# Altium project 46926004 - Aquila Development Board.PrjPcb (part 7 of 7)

## Sheet 900_Display_Port.SchDoc: Aquila Development Board
size Letter; Organization: Toradex Solutions Inc.; Address1: 6415 Northwest Drive; Address2: Mississauga, ON, L4V 1X1; Address3: Canada; SheetNumber: 34; SheetTotal: 34
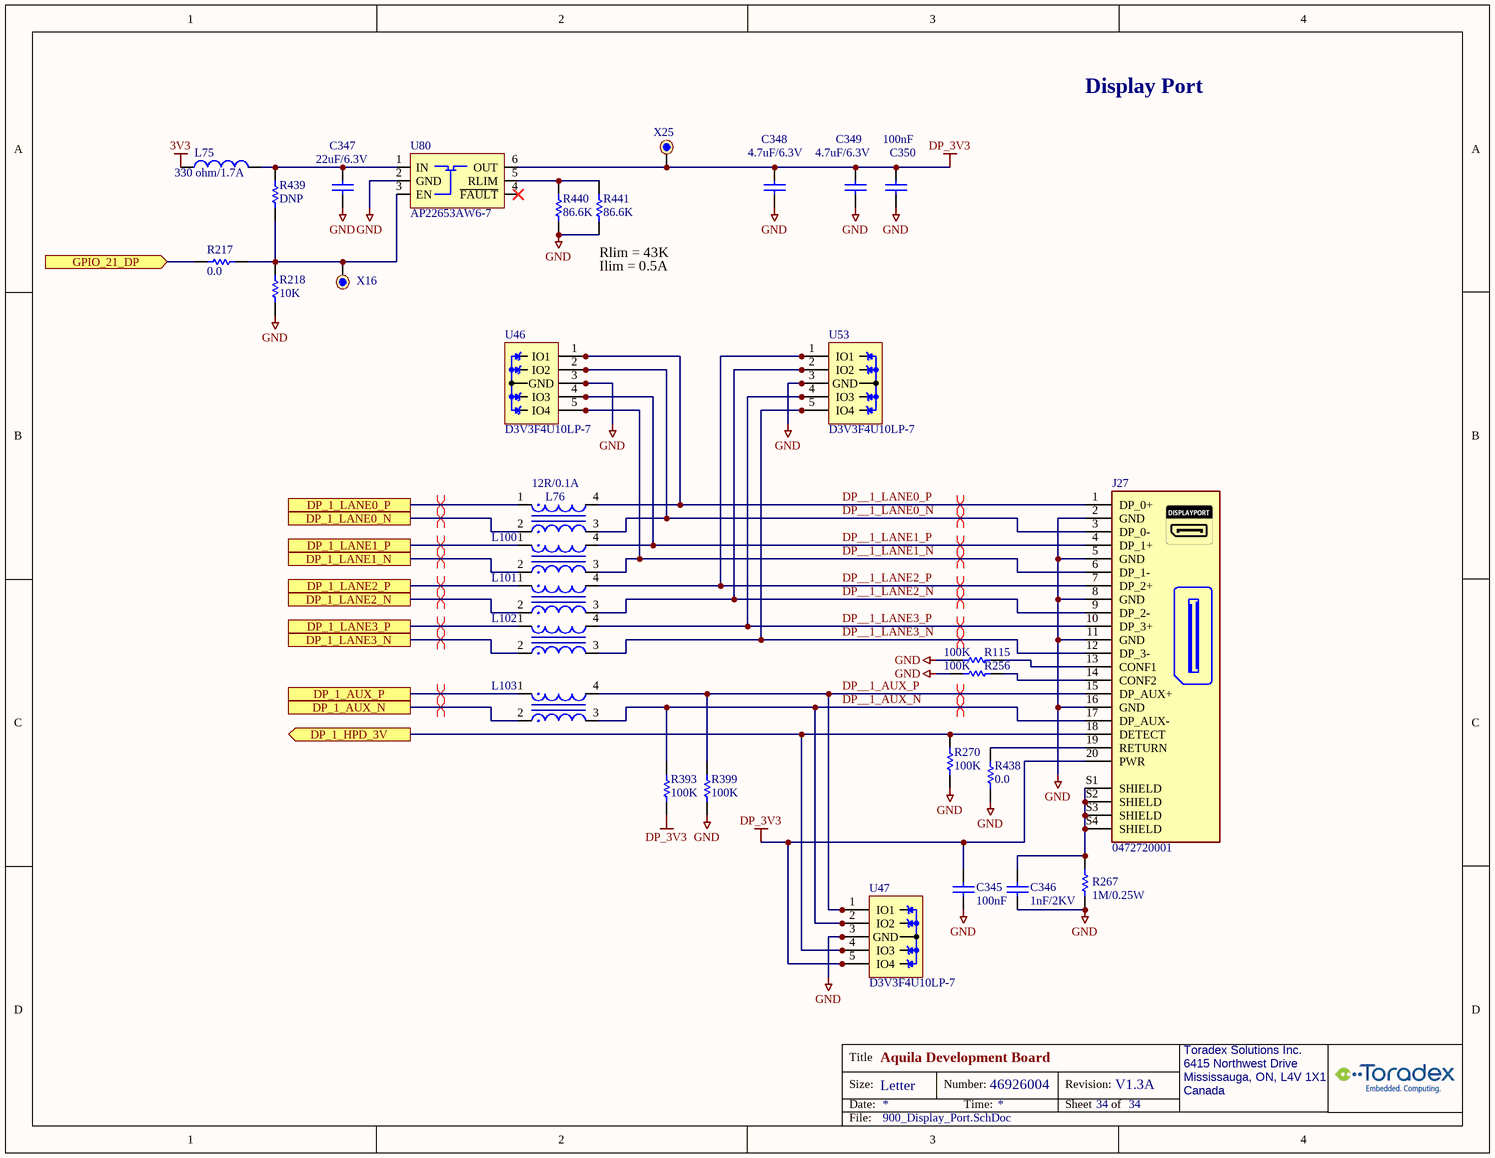
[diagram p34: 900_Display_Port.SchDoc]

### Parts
C345  100nF  [C0402_CAPC1005L]
C346  value 1nF/2KV  [C/1206]  (hidden comment: 0567-Cap-1206-1nF/2KV)
C347  22uF/6.3V  [C0402_CAPC1005L]
C348  value 4.7uF/6.3V  [C0402_CAPC1005L]  (hidden comment: 0354-Cap-0402-4.7uF/6.3V)
C349  value 4.7uF/6.3V  [C0402_CAPC1005L]  (hidden comment: 0354-Cap-0402-4.7uF/6.3V)
C350  100nF  [C0402_CAPC1005L]
J27  0472720001  [MOLEX_47272-0001]
L75  value 330 ohm/1.7A  [C/0603]  (hidden comment: 0405-Fer-0603-330ohm/1.7A)
L76  12R/0.1A  [COIL0302]
L100  12R/0.1A  [COIL0302]  (value not drawn)
L101  12R/0.1A  [COIL0302]  (value not drawn)
L102  12R/0.1A  [COIL0302]  (value not drawn)
L103  12R/0.1A  [COIL0302]  (value not drawn)
R115  value 100K  [R0402_RESC1005L]  (hidden comment: 1977-Res-0402-100K)
R217  value 0.0  [R/0603]  (hidden comment: 0195-Res-0603-0.0ohm)
R218  value 10K  [R0402_RESC1005L]  (hidden comment: 1572-Res-0402-10K)
R256  value 100K  [R0402_RESC1005L]  (hidden comment: 1977-Res-0402-100K)
R267  value 1M/0.25W  [R/1206]  (hidden comment: 1860-Res-1206-1M-5%-0.25W)
R270  value 100K  [R0402_RESC1005L]  (hidden comment: 1977-Res-0402-100K)
R393  value 100K  [R0402_RESC1005L]  (hidden comment: 1977-Res-0402-100K)
R399  value 100K  [R0402_RESC1005L]  (hidden comment: 1977-Res-0402-100K)
R438  value 0.0  [R/0603]  (hidden comment: 0195-Res-0603-0.0ohm)
R439  value DNP  [R/0603]  (hidden comment: 0000-Res-0603-DNP)
R440  value 86.6K  [R0402_RESC1005L]  (hidden comment: 1539-Res-0402-86.6k)
R441  value 86.6K  [R0402_RESC1005L]  (hidden comment: 1539-Res-0402-86.6k)
U46  D3V3F4U10LP-7  [10-UFDFN]
U47  D3V3F4U10LP-7  [10-UFDFN]
U53  D3V3F4U10LP-7  [10-UFDFN]
U80  AP22653AW6-7  [SOT23-6]
X16  000-TestPoint  [TestPoint_1]  (value not drawn)
X25  000-TestPoint  [TestPoint_1]  (value not drawn)

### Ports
DP_1_AUX_N, DP_1_AUX_P, DP_1_HPD_3V (out), DP_1_LANE0_N, DP_1_LANE0_P, DP_1_LANE1_N, DP_1_LANE1_P, DP_1_LANE2_N, DP_1_LANE2_P, DP_1_LANE3_N, DP_1_LANE3_P, GPIO_21_DP (in)

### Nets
3V3: L75.1
DP_3V3: C345.2 C348.2 C349.2 C350.2 J27.20(PWR) R393.1 U47.5(IO4) U47.6(NC) U80.6(OUT) X25.1
GND: C345.1 C346.1 C347.1 C348.1 C349.1 C350.1 J27.2(GND) J27.5(GND) J27.8(GND) J27.11(GND) J27.16(GND) R115.2 R218.2 R256.2 R267.2 R270.2 R399.1 R438.1 R440.1 R441.1 U46.3(GND) U46.8(GND) U47.3(GND) U47.8(GND) U53.3(GND) U53.8(GND) U80.2(GND)
DP_1_AUX_N: L103.2 ; port DP_1_AUX_N
DP_1_AUX_P: L103.1 ; port DP_1_AUX_P
DP_1_HPD_3V: J27.18(DETECT) R270.1 U47.4(IO3) U47.7(NC) ; port DP_1_HPD_3V
DP_1_LANE0_N: L76.2 ; port DP_1_LANE0_N
DP_1_LANE0_P: L76.1 ; port DP_1_LANE0_P
DP_1_LANE1_N: L100.2 ; port DP_1_LANE1_N
DP_1_LANE1_P: L100.1 ; port DP_1_LANE1_P
DP_1_LANE2_N: L101.2 ; port DP_1_LANE2_N
DP_1_LANE2_P: L101.1 ; port DP_1_LANE2_P
DP_1_LANE3_N: L102.2 ; port DP_1_LANE3_N
DP_1_LANE3_P: L102.1 ; port DP_1_LANE3_P
DP__1_AUX_N: J27.17(DP_AUX-) L103.3 R393.2 U47.2(IO2) U47.9(NC)
DP__1_AUX_P: J27.15(DP_AUX+) L103.4 R399.2 U47.1(IO1) U47.10(NC)
DP__1_LANE0_N: J27.3(DP_0-) L76.3 U46.2(IO2) U46.9(NC)
DP__1_LANE0_P: J27.1(DP_0+) L76.4 U46.1(IO1) U46.10(NC)
DP__1_LANE1_N: J27.6(DP_1-) L100.3 U46.5(IO4) U46.6(NC)
DP__1_LANE1_P: J27.4(DP_1+) L100.4 U46.4(IO3) U46.7(NC)
DP__1_LANE2_N: J27.9(DP_2-) L101.3 U53.2(IO2) U53.9(NC)
DP__1_LANE2_P: J27.7(DP_2+) L101.4 U53.1(IO1) U53.10(NC)
DP__1_LANE3_N: J27.12(DP_3-) L102.3 U53.5(IO4) U53.6(NC)
DP__1_LANE3_P: J27.10(DP_3+) L102.4 U53.4(IO3) U53.7(NC)
GPIO_21_DP: R217.2 ; port GPIO_21_DP
NetC346_2: C346.2 J27.S1(SHIELD) J27.S2(SHIELD) J27.S3(SHIELD) J27.S4(SHIELD) R267.1
NetC347_2: C347.2 L75.2 R439.1 U80.1(IN)
NetJ27_13: J27.13(CONF1) R115.1
NetJ27_14: J27.14(CONF2) R256.1
NetJ27_19: J27.19(RETURN) R438.2
NetR217_1: R217.1 R218.1 R439.2 U80.3(EN) X16.1
NetR440_2: R440.2 R441.2 U80.5(RLIM)

Not connected (* = marked no-connect by the designer): U80 4(~{FAULT})*

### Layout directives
differential pair; differential pair class DP: DP_1_AUX_N, DP_1_AUX_P, DP_1_LANE0_N, DP_1_LANE0_P, DP_1_LANE1_N, DP_1_LANE1_P, DP_1_LANE2_N, DP_1_LANE2_P, DP_1_LANE3_N, DP_1_LANE3_P
differential pair; differential pair class DP_CON: DP__1_AUX_N, DP__1_AUX_P, DP__1_LANE0_N, DP__1_LANE0_P, DP__1_LANE1_N, DP__1_LANE1_P, DP__1_LANE2_N, DP__1_LANE2_P, DP__1_LANE3_N, DP__1_LANE3_P

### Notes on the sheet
- Display Port
- (near R441) Rlim = 43K
- Ilim = 0.5A

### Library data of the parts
C345 C350 = 1566-Cap-0402-100nF/50V: (-55 to 125 DegC AEC) Cap Ceramic 0.1uF 50V X7R 10% 0402; MfrNo: GRT155R71H104KE01D; Mfr: Murata; Alt: CL05B104KB54PNC,GCM155R71H104ME02D,GCM155R71H104KE02D,GCM155R71H104KE02J; PN: 1566
C346 = 0567-Cap-1206-1nF/2KV: (-55 to 125 DegC) CAP CER 1000PF 2KV X7R 1206; Mfr: Johanson Dielectrics Inc.; MfrNo: 202R18W102KV4E; PN: 567; Alt: 478-2956-1-ND; Alt2: 399-4819-1-ND
C347 = 2404-Cap-0402-22uF/6.3V: (-55 to 85 DegC) CAP CER 22UF 6.3V 20% X5R 0402; MfrNo: GRM155R60J226ME11D; Mfr: Murata; PN: 2404
C348 C349 = 0354-Cap-0402-4.7uF/6.3V: (-55 to 85 DegC) CAP CER 4.7UF 6.3V 20% X5R 0402; MfrNo: GRM155R60J475ME87D; Mfr: Murata Electronics North America; PN: 354; Alt: 1276-1483-1-ND; Alt2: 490-5915-1-ND
J27 = 2274-CONN-DISPLAY-PORT: (-20 to 85 DegC) CONN RCPT DISPLAYPORT 20P SMD RA/TH; Mfr: Molex; MfrNo: 47272-0001; PN: 2274
L75 = 0405-Fer-0603-330ohm/1.7A: (-55 to 125 DegC) FERRITE BEAD 330 OHM 0603 1.7A 80mohm, typ 48mohm; Mfr: TDK Corporation; MfrNo: MPZ1608S331ATA00; PN: 405; TR: 445-5221-2-ND; DR: 445-5221-6-ND; DR2: 810-MPZ1608S331ATA00
L76 L100-L103 = 1371-Ind-0.8x0.6-12ohm/0.1A-Choke: (-40 to 85 DegC) Ind CMC Choke 12 Ohm 0.1A 1ohm 0.85x0.65x0.5mm; MfrNo: EXC-14CH120U; Mfr: Panasonic; PN: 1371
R115 R256 R270 R393 R399 = 1977-Res-0402-100K: (-55 to 155 DegC) RES 100K OHM 1/16W 1% 0402 SMD; Mfr: Yageo; MfrNo: RC0402FR-07100KL; PN: 1977
R217 R438 = 0195-Res-0603-0.0ohm: (-55 to 155 DegC) RES 0.0 OHM 1/10W JUMP 0603; Mfr: Samsung; MfrNo: RC1608J000CS; Alt: 311-0.0GRCT-ND; Alt2: A106051CT-ND; PN: 195; TR: 1276-3510-2-ND
R218 = 1572-Res-0402-10K: (-55 to 155 DegC AEC) RES 10K OHM 1% 1/16W 100ppm 0402; Mfr: Stackpole Electronics; MfrNo: RMCF0402FT10K0; Alt: AC0402FR-0710KL,AC0402FR-1310KL,CRGCQ0402F10K; PN: 1572
R267 = 1860-Res-1206-1M-5%-0.25W: (-55 to 155 DegC) RES SMD 1M OHM 5% 0.25W 10ppm 1206; Mfr: TE Connectivity; MfrNo: CRGCQ1206J1M0; PN: 1860; Alt: RMCF1206JT1M00, RMCF1206JG1M00, CR1206-JW-105ELF
R439 = 0000-Res-0603-DNP: RES 0603
R440 R441 = 1539-Res-0402-86.6k: (-55 to 155 DegC AEC) RES 86.6K OHM 1% 1/16W 100ppm 0402; Mfr: Stackpole Electronics; MfrNo: RMCF0402FT86K6; Alt: AC0402FR-0786K6L,RK73H1ETTP8662F,ERJ-2RKF8662X; PN: 1539
U46 U47 U53 = 1463-D3V3F4U10LP: (-55 to 150 DegC) IC TVS DIODE 4ch Vrm:3.3V Vbr:6.2 Vcl:5V@16A 12KV/12KV 0.5pF 10-UFDFN 0.5mm; Mfr: Diodes; PN: 1463; Notes: Similar: PN1317
U80 = 1475-AP22653: (-40 to 85 DegC) IC PWR SWITCH 3-5.5V EN-Active-High ENth:1.5V With-Discharge 65mohm typ ADJ 0.1-2.1A 6SSOP; Mfr: Diodes; PN: 1475; Note: Similar: BD2222G, BD2242G, TPS25221, TPS2553, RT9728A, RT9728B, RT9728C, AP2553, MIC2009YM6, MIC2019YM6, MIC2009A-1YM6,MIC2019A-1YM6
X16 X25 = 000-TestPoint: TestPoint TH; Note: this is PCB footprint only, no parts to buy or assemble

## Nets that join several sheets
1V8: 200_Aquila (R66.1), 600_Peripherals (14 pins), 100_Power_1 (J15.6 J16.6), 210_Translators (6 pins), 300_USB1_OTG (L21.1 R108.1 R118.1), 310_USB3 (R140.1 R141.1), 400_M2_KeyB (R182.1 R193.1 R418.2), 420_MIPI_DSI (16 pins), 500_CAN (L57.1), 120_Power_2 (Q5.1 R39.2 X19.1), 140_Power_3 (C8.2 U3.2), 360_Ethernet2 (5 pins), 410_M2_KeyM (R198.1), 540_Audio (6 pins), 620_Peripherals2 (15 pins), 225_Debug2 (8 pins), 227_JTAG (C239.2 R284.2 U61.1 U61.16), 215_Translators2 (25 pins), 800_Jumpers (10 pins), 810_Jumpers (18 pins), 510_ISO_CAN (L72.1), 700_RS232_RS485 (10 pins), 315_USBC_DFP (R391.2 R392.1), 445_CSI_1 (7 pins), 450_CSI_2 (7 pins)
3V3: 200_Aquila (R459.1), 100_Power_1 (J15.4 J15.5 J16.4 J16.5), 210_Translators (9 pins), 220_Debug (L15.1), 300_USB1_OTG (10 pins), 305_USB_Hub (C129.2 L31.2 Q13.2 R135.2), 350_Ethernet (J34.11 J34.13), 230_SD_Card (L20.1), 400_M2_KeyB (L46.1 L47.1), 420_MIPI_DSI (6 pins), 120_Power_2 (6 pins), 140_Power_3 (7 pins), 360_Ethernet2 (J36.11 J36.13 L41.2 L42.2), 410_M2_KeyM (L48.1 L49.1), 225_Debug2 (6 pins), 215_Translators2 (14 pins), 810_Jumpers (J13.9 J13.10), 325_USB_PowerDelivery (R402.1 R403.1), 700_RS232_RS485 (L79.1 L80.1), 315_USBC_DFP (5 pins), 445_CSI_1 (7 pins), 450_CSI_2 (7 pins), 900_Display_Port (L75.1)
3V3_UHUB: 200_Aquila (R65.1), 305_USB_Hub (18 pins)
5V: 120_Power_2 (7 pins), 140_Power_3 (7 pins), 160_Power_4 (11 pins)
5V_S: 100_Power_1 (J15.2 J16.2), 300_USB1_OTG (5 pins), 310_USB3 (L32.1 L33.1), 305_USB_Hub (R123.2), 420_MIPI_DSI (6 pins), 500_CAN (L56.1), 120_Power_2 (R40.2), 140_Power_3 (Q3.D R24.2 X11.1), 360_Ethernet2 (R159.2 R160.2), 620_Peripherals2 (13 pins), 510_ISO_CAN (L71.1), 315_USBC_DFP (6 pins), 445_CSI_1 (C316.2 J70.21), 450_CSI_2 (C322.2 J71.21)
5V_STB: 100_Power_1 (C4.2 U1.3 X1.1), 120_Power_2 (7 pins)
5V_T: 200_Aquila (28 pins), 600_Peripherals (R239.1 R358.1), 140_Power_3 (6 pins), 227_JTAG (L66.1)
12V: 120_Power_2 (10 pins), 620_Peripherals2 (C237.2 J56.2 R274.2 U40.2)
D_1V8_LDO: 220_Debug (C41.1 U86.5), 225_Debug2 (J63.1)
FT_3V3: 220_Debug (D12.3 X30.1), 225_Debug2 (10 pins), 227_JTAG (C240.2 U61.15)
GND: 200_Aquila (111 pins), 600_Peripherals (26 pins), 100_Power_1 (19 pins), 210_Translators (9 pins), 220_Debug (15 pins), 300_USB1_OTG (36 pins), 310_USB3 (30 pins), 305_USB_Hub (37 pins), 350_Ethernet (7 pins), 230_SD_Card (14 pins), 400_M2_KeyB (41 pins), 420_MIPI_DSI (20 pins), 500_CAN (18 pins), 120_Power_2 (58 pins), 140_Power_3 (10 pins), 360_Ethernet2 (67 pins), 410_M2_KeyM (39 pins), 540_Audio (39 pins), 620_Peripherals2 (32 pins), 225_Debug2 (58 pins), 227_JTAG (14 pins), 215_Translators2 (20 pins), 800_Jumpers (8 pins), 810_Jumpers (18 pins), 160_Power_4 (30 pins), 510_ISO_CAN (18 pins), 325_USB_PowerDelivery (37 pins), 700_RS232_RS485 (17 pins), 315_USBC_DFP (29 pins), 445_CSI_1 (19 pins), 450_CSI_2 (19 pins), 900_Display_Port (27 pins)
SHLD1: 000_Main (H1.0), 100_Power_1 (R447.1)
SHLD2: 000_Main (H2.0), 100_Power_1 (R448.1)
SHLD3: 000_Main (H3.0), 100_Power_1 (R449.1)
SHLD4: 000_Main (H4.0), 100_Power_1 (R11.1)
VIN: 100_Power_1 (8 pins), 420_MIPI_DSI (L55.2), 120_Power_2 (6 pins), 160_Power_4 (15 pins)
VPD: 100_Power_1 (D3.1 D3.2), 325_USB_PowerDelivery (F2.2 R339.1)
5V_ENABLE: 120_Power_2 (R64.2), 160_Power_4 (5 pins)
ADC_1: 200_Aquila (M1.D01), 600_Peripherals (RA7.1)
ADC_2: 200_Aquila (M1.D02), 600_Peripherals (RA7.2)
ADC_3: 200_Aquila (M1.D03), 600_Peripherals (RA7.3)
ADC_4: 200_Aquila (M1.D04), 600_Peripherals (RA7.4)
CAN_1_RX: 200_Aquila (M1.B49), 800_Jumpers (RA16.1)
CAN_1_RX_JMP: 800_Jumpers (J1.8 J1B.4), 510_ISO_CAN (U67.3)
CAN_1_TX: 200_Aquila (M1.B48), 800_Jumpers (RA16.2)
CAN_1_TX_JMP: 800_Jumpers (J1.6 J1B.3), 510_ISO_CAN (R67.2 U67.2)
CAN_2_RX: 200_Aquila (M1.B51), 800_Jumpers (RA21.3)
CAN_2_RX_JMP: 800_Jumpers (J1.12 J1B.6), 510_ISO_CAN (U68.3)
CAN_2_TX: 200_Aquila (M1.B50), 800_Jumpers (RA21.4)
CAN_2_TX_JMP: 800_Jumpers (J1.10 J1B.5), 510_ISO_CAN (R68.2 U68.2)
CAN_3_RX: 200_Aquila (M1.B54), 800_Jumpers (RA21.1)
CAN_3_RX_JMP: 500_CAN (U49.4), 800_Jumpers (J1.16 J1B.8)
CAN_3_TX: 200_Aquila (M1.B53), 800_Jumpers (RA21.2)
CAN_3_TX_JMP: 500_CAN (R43.2 U49.1), 800_Jumpers (J1.14 J1B.7)
CAN_4_RX: 200_Aquila (M1.B56), 800_Jumpers (RA17.2)
CAN_4_RX_JMP: 500_CAN (U48.4), 800_Jumpers (J1.20 J1B.10)
CAN_4_TX: 200_Aquila (M1.B55), 800_Jumpers (RA17.1)
CAN_4_TX_JMP: 500_CAN (R50.2 U48.1), 800_Jumpers (J1.18 J1B.9)
CSI_1_CLK_N: 200_Aquila (M1.A23), 445_CSI_1 (L83.1)
CSI_1_CLK_P: 200_Aquila (M1.A22), 445_CSI_1 (L83.2)
CSI_1_D0_N: 200_Aquila (M1.A29), 445_CSI_1 (L81.1)
CSI_1_D0_P: 200_Aquila (M1.A28), 445_CSI_1 (L81.2)
CSI_1_D1_N: 200_Aquila (M1.A26), 445_CSI_1 (L82.1)
CSI_1_D1_P: 200_Aquila (M1.A25), 445_CSI_1 (L82.2)
CSI_1_D2_N: 200_Aquila (M1.A20), 445_CSI_1 (L84.1)
CSI_1_D2_P: 200_Aquila (M1.A19), 445_CSI_1 (L84.2)
CSI_1_D3_N: 200_Aquila (M1.A17), 445_CSI_1 (L85.1)
CSI_1_D3_P: 200_Aquila (M1.A16), 445_CSI_1 (L85.2)
CSI_2_CLK_N: 200_Aquila (M1.B09), 450_CSI_2 (L88.1)
CSI_2_CLK_P: 200_Aquila (M1.B08), 450_CSI_2 (L88.2)
CSI_2_D0_N: 200_Aquila (M1.B15), 450_CSI_2 (L86.1)
CSI_2_D0_P: 200_Aquila (M1.B14), 450_CSI_2 (L86.2)
CSI_2_D1_N: 200_Aquila (M1.B12), 450_CSI_2 (L87.1)
CSI_2_D1_P: 200_Aquila (M1.B11), 450_CSI_2 (L87.2)
CSI_2_D2_N: 200_Aquila (M1.B06), 450_CSI_2 (L89.1)
CSI_2_D2_P: 200_Aquila (M1.B05), 450_CSI_2 (L89.2)
CSI_2_D3_N: 200_Aquila (M1.B03), 450_CSI_2 (L90.1)
CSI_2_D3_P: 200_Aquila (M1.B02), 450_CSI_2 (L90.2)
CTRL_FORCE_OFF_MOCI#: 200_Aquila (M1.B94), 810_Jumpers (RA30.4)
CTRL_FORCE_OFF_MOCI#JMP: 120_Power_2 (J47.5 R54.2), 225_Debug2 (J19.8), 810_Jumpers (J7.8 J7B.4)
CTRL_MCLK_3V: 215_Translators2 (U44.14), 445_CSI_1 (R359.2), 450_CSI_2 (R367.2)
CTRL_MCLK_JMP: 215_Translators2 (RA10.1 U44.3), 810_Jumpers (J7.16 J7B.8)
CTRL_MCLK_MOCI: 200_Aquila (M1.A14), 810_Jumpers (RA33.1)
CTRL_PWR_BTN_MICO#: 200_Aquila (M1.B93), 810_Jumpers (RA30.3)
CTRL_PWR_BTN_MICO#JMP: 120_Power_2 (J47.4 U8.5), 225_Debug2 (J19.4), 810_Jumpers (J7.6 J7B.3)
CTRL_PWR_EN_MOCI: 200_Aquila (M1.B95), 810_Jumpers (RA33.4)
CTRL_PWR_EN_MOCI_JMP: 420_MIPI_DSI (J44.59), 120_Power_2 (Q7.2 R56.1), 810_Jumpers (J7.10 J7B.5)
CTRL_RECOVERY_MICO#: 200_Aquila (M1.B91), 810_Jumpers (RA30.1)
CTRL_RECOVERY_MICO#JMP: 600_Peripherals (B8.3 D35.1), 225_Debug2 (J19.6), 810_Jumpers (J7.2 J7B.1)
CTRL_RESET_MICO#: 200_Aquila (M1.B92), 810_Jumpers (RA30.2)
CTRL_RESET_MICO#JMP: 600_Peripherals (B7.3 D33.1), 120_Power_2 (J47.6), 225_Debug2 (J19.2), 227_JTAG (R464.1), 810_Jumpers (J7.4 J7B.2)
CTRL_RESET_MOCI#: 200_Aquila (M1.D05), 810_Jumpers (RA33.2)
CTRL_RESET_MOCI#JMP: 600_Peripherals (D34.2 R358.2), 305_USB_Hub (D19.3), 420_MIPI_DSI (J44.57), 360_Ethernet2 (R400.2), 810_Jumpers (J7.12 J7B.6)
CTRL_TAMPER0: 200_Aquila (M1.C14), 800_Jumpers (RA29.1)
CTRL_TAMPER1: 200_Aquila (M1.C15), 800_Jumpers (RA29.2)
CTRL_WAKE1_MICO#: 200_Aquila (M1.D06), 810_Jumpers (RA33.3)
DP_1_AUX_N: 200_Aquila (M1.A46), 900_Display_Port (L103.2)
DP_1_AUX_P: 200_Aquila (M1.A47), 900_Display_Port (L103.1)
DP_1_HPD: 200_Aquila (M1.B59), 810_Jumpers (J92.2)
DP_1_HPD_3V: 215_Translators2 (U44.11), 900_Display_Port (J27.18 R270.1 U47.4 U47.7)
DP_1_HPD_JMP: 215_Translators2 (RA10.4 U44.6), 810_Jumpers (J92.1)
DP_1_LANE0_N: 200_Aquila (M1.A58), 900_Display_Port (L76.2)
DP_1_LANE0_P: 200_Aquila (M1.A59), 900_Display_Port (L76.1)
DP_1_LANE1_N: 200_Aquila (M1.A55), 900_Display_Port (L100.2)
DP_1_LANE1_P: 200_Aquila (M1.A56), 900_Display_Port (L100.1)
DP_1_LANE2_N: 200_Aquila (M1.A52), 900_Display_Port (L101.2)
DP_1_LANE2_P: 200_Aquila (M1.A53), 900_Display_Port (L101.1)
DP_1_LANE3_N: 200_Aquila (M1.A49), 900_Display_Port (L102.2)
DP_1_LANE3_P: 200_Aquila (M1.A50), 900_Display_Port (L102.1)
DSI_1_CLK_N: 200_Aquila (M1.A37), 420_MIPI_DSI (L52.2)
DSI_1_CLK_P: 200_Aquila (M1.A38), 420_MIPI_DSI (L52.1)
DSI_1_D0_N: 200_Aquila (M1.A43), 420_MIPI_DSI (L50.2)
DSI_1_D0_P: 200_Aquila (M1.A44), 420_MIPI_DSI (L50.1)
DSI_1_D1_N: 200_Aquila (M1.A40), 420_MIPI_DSI (L51.2)
DSI_1_D1_P: 200_Aquila (M1.A41), 420_MIPI_DSI (L51.1)
DSI_1_D2_N: 200_Aquila (M1.A34), 420_MIPI_DSI (L53.2)
DSI_1_D2_P: 200_Aquila (M1.A35), 420_MIPI_DSI (L53.1)
DSI_1_D3_N: 200_Aquila (M1.A31), 420_MIPI_DSI (L54.2)
DSI_1_D3_P: 200_Aquila (M1.A32), 420_MIPI_DSI (L54.1)
ETH_1_LED1: 200_Aquila (M1.A99), 350_Ethernet (R147.1)
ETH_1_LED2: 200_Aquila (M1.A100), 350_Ethernet (R146.1)
ETH_1_MDI0_N: 200_Aquila (M1.A89), 350_Ethernet (J34.8 U33.2 U33.9)
ETH_1_MDI0_P: 200_Aquila (M1.A88), 350_Ethernet (J34.9 U33.1 U33.10)
ETH_1_MDI1_N: 200_Aquila (M1.A92), 350_Ethernet (J34.6 U33.5 U33.6)
ETH_1_MDI1_P: 200_Aquila (M1.A91), 350_Ethernet (J34.7 U33.4 U33.7)
ETH_1_MDI2_N: 200_Aquila (M1.A95), 350_Ethernet (J34.4 U34.2 U34.9)
ETH_1_MDI2_P: 200_Aquila (M1.A94), 350_Ethernet (J34.5 U34.1 U34.10)
ETH_1_MDI3_N: 200_Aquila (M1.A98), 350_Ethernet (J34.2 U34.5 U34.6)
ETH_1_MDI3_P: 200_Aquila (M1.A97), 350_Ethernet (J34.3 U34.4 U34.7)
ETH_2_XGMII_INT#: 200_Aquila (M1.B81), 360_Ethernet2 (J35.3 R174.1 U37.44)
ETH_2_XGMII_MDC: 200_Aquila (M1.B90), 360_Ethernet2 (J35.2 U37.16)
ETH_2_XGMII_MDIO: 200_Aquila (M1.B89), 360_Ethernet2 (J35.1 R175.1 U37.17)
ETH_2_XGMII_RX_N: 200_Aquila (M1.B83), 360_Ethernet2 (C188.2)
ETH_2_XGMII_RX_P: 200_Aquila (M1.B84), 360_Ethernet2 (C147.2)
ETH_2_XGMII_TX_N: 200_Aquila (M1.B86), 360_Ethernet2 (U37.28)
ETH_2_XGMII_TX_P: 200_Aquila (M1.B87), 360_Ethernet2 (U37.27)
FT_USB_N: 220_Debug (L14.1), 225_Debug2 (U15.7)
FT_USB_P: 220_Debug (L14.4), 225_Debug2 (U15.8)
FTB_TCK: 225_Debug2 (J25.5 U15.26), 227_JTAG (U61.13)
FTB_TDI: 225_Debug2 (J25.4 U15.27), 227_JTAG (U61.11)
FTB_TDO: 225_Debug2 (J25.3 U15.28), 227_JTAG (U61.14)
FTB_TMS: 225_Debug2 (J25.2 U15.29), 227_JTAG (U61.12)
GPIO_01: 200_Aquila (M1.D23), 810_Jumpers (RA34.4)
GPIO_02: 200_Aquila (M1.D24), 810_Jumpers (RA34.3)
GPIO_03: 200_Aquila (M1.D25), 810_Jumpers (RA34.2)
GPIO_04: 200_Aquila (M1.C20), 810_Jumpers (RA34.1)
GPIO_05: 200_Aquila (M1.C21), 810_Jumpers (RA36.4)
GPIO_06: 200_Aquila (M1.C22), 810_Jumpers (RA36.3)
GPIO_07: 200_Aquila (M1.C23), 810_Jumpers (RA36.2)
GPIO_08: 200_Aquila (M1.C24), 810_Jumpers (RA36.1)
GPIO_09_CSI_1: 200_Aquila (M1.B17), 800_Jumpers (RA24.4)
GPIO_09_CSI_1_JMP: 800_Jumpers (J6.2 J6B.1), 445_CSI_1 (R360.2 U82.3)
GPIO_10_CSI_1: 200_Aquila (M1.B18), 800_Jumpers (RA24.3)
GPIO_10_CSI_1_JMP: 800_Jumpers (J6.4 J6B.2), 445_CSI_1 (R361.2 U82.4)
GPIO_11_CSI_1: 200_Aquila (M1.A11), 800_Jumpers (RA24.2)
GPIO_11_CSI_1_JMP: 800_Jumpers (J6.6 J6B.3), 445_CSI_1 (U82.5)
GPIO_12_CSI_1: 200_Aquila (M1.B19), 800_Jumpers (RA24.1)
GPIO_12_CSI_1_JMP: 800_Jumpers (J6.8 J6B.4), 445_CSI_1 (R362.2 U82.6)
GPIO_13_CSI_2: 200_Aquila (M1.C01), 800_Jumpers (RA27.1)
GPIO_13_CSI_2_JMP: 800_Jumpers (J6.20 J6B.10), 450_CSI_2 (R368.2 U89.3)
GPIO_14_CSI_2: 200_Aquila (M1.C02), 800_Jumpers (RA27.2)
GPIO_14_CSI_2_JMP: 800_Jumpers (J6.18 J6B.9), 450_CSI_2 (R369.2 U89.4)
GPIO_15_CSI_2: 200_Aquila (M1.C03), 800_Jumpers (RA26.4)
GPIO_15_CSI_2_JMP: 800_Jumpers (J6.16 J6B.8), 450_CSI_2 (U89.5)
GPIO_16_CSI_2: 200_Aquila (M1.C04), 800_Jumpers (RA26.3)
GPIO_16_CSI_2_JMP: 800_Jumpers (J6.14 J6B.7), 450_CSI_2 (R370.2 U89.6)
GPIO_17_DSI_1: 200_Aquila (M1.B42), 800_Jumpers (RA20.4)
GPIO_17_DSI_1_JMP: 420_MIPI_DSI (J44.8), 800_Jumpers (J5.10 J5B.5)
GPIO_18_DSI_1: 200_Aquila (M1.B43), 800_Jumpers (RA14.1)
GPIO_18_DSI_1_JMP: 420_MIPI_DSI (JP3.2), 800_Jumpers (J5.8 J5B.4)
GPIO_19_DSI_1: 200_Aquila (M1.B44), 800_Jumpers (RA14.2)
GPIO_19_DSI_1_JMP: 420_MIPI_DSI (JP4.2), 800_Jumpers (J5.6 J5B.3)
GPIO_20_DSI_1: 200_Aquila (M1.B45), 800_Jumpers (RA14.3)
GPIO_20_DSI_1_JMP: 420_MIPI_DSI (J44.56), 800_Jumpers (J5.4 J5B.2)
GPIO_21_DP: 200_Aquila (M1.B57), 900_Display_Port (R217.2)
I2C1_SCL_3V: 210_Translators (R73.2 U9.6), 305_USB_Hub (RA4.1), 810_Jumpers (J13.2)
I2C1_SDA_3V: 210_Translators (R71.2 U9.5), 305_USB_Hub (RA4.2), 810_Jumpers (J13.1)
I2C2_SCL_3V: 210_Translators (R74.2 U10.6), 810_Jumpers (J13.5)
I2C2_SDA_3V: 210_Translators (R72.2 U10.5), 810_Jumpers (J13.4)
I2C6_SCL_3V: 210_Translators (R79.2 U11.6), 810_Jumpers (J13.8)
I2C6_SDA_3V: 210_Translators (R78.2 U11.5), 810_Jumpers (J13.7)
I2C_1_SCL: 200_Aquila (M1.D08), 810_Jumpers (RA15.2)
I2C_1_SCL_JMP: 600_Peripherals (U54.2 U55.6), 210_Translators (U9.3), 300_USB1_OTG (U19.3), 140_Power_3 (U3.3), 540_Audio (U52.2), 620_Peripherals2 (U57.3), 810_Jumpers (J10.4 J10B.2 R478.2)
I2C_1_SDA: 200_Aquila (M1.D07), 810_Jumpers (RA15.1)
I2C_1_SDA_JMP: 600_Peripherals (U54.1 U55.5), 210_Translators (U9.4), 300_USB1_OTG (U19.4), 140_Power_3 (U3.4), 540_Audio (U52.3), 620_Peripherals2 (U57.4), 810_Jumpers (J10.2 J10B.1 R477.2)
I2C_2_SCL: 200_Aquila (M1.C17), 810_Jumpers (RA45.3)
I2C_2_SCL_JMP: 210_Translators (U10.3), 810_Jumpers (J11.4 J11B.2 R414.2)
I2C_2_SDA: 200_Aquila (M1.C16), 810_Jumpers (RA45.4)
I2C_2_SDA_JMP: 210_Translators (U10.4), 810_Jumpers (J11.2 J11B.1 R413.2)
I2C_3_DSI1_SCL: 200_Aquila (M1.B41), 800_Jumpers (RA20.1)
I2C_3_DSI1_SDA: 200_Aquila (M1.B40), 800_Jumpers (RA20.2)
I2C_3_DSI_SCL_JMP: 420_MIPI_DSI (U85.12), 800_Jumpers (J5.16 J5B.8 R76.2)
I2C_3_DSI_SDA_JMP: 420_MIPI_DSI (U85.13), 800_Jumpers (J5.14 J5B.7 R75.2)
I2C_4_CSI1_SCL: 200_Aquila (M1.A13), 800_Jumpers (RA26.1)
I2C_4_CSI1_SCL_JMP: 800_Jumpers (J6.12 J6B.6 R410.1), 445_CSI_1 (U81.3)
I2C_4_CSI1_SDA: 200_Aquila (M1.A12), 800_Jumpers (RA26.2)
I2C_4_CSI1_SDA_JMP: 800_Jumpers (J6.10 J6B.5 R409.1), 445_CSI_1 (U81.4)
I2C_5_CSI2_SCL: 200_Aquila (M1.C06), 800_Jumpers (RA27.4)
I2C_5_CSI2_SCL_JMP: 800_Jumpers (J6.24 J6B.12 R412.1), 450_CSI_2 (U88.3)
I2C_5_CSI2_SDA: 200_Aquila (M1.C05), 800_Jumpers (RA27.3)
I2C_5_CSI2_SDA_JMP: 800_Jumpers (J6.22 J6B.11 R411.1), 450_CSI_2 (U88.4)
I2C_6_SCL: 200_Aquila (M1.C19), 810_Jumpers (RA45.1)
I2C_6_SCL_JMP: 210_Translators (U11.3), 810_Jumpers (J11.8 J11B.4 R427.2)
I2C_6_SDA: 200_Aquila (M1.C18), 810_Jumpers (RA45.2)
I2C_6_SDA_JMP: 210_Translators (U11.4), 810_Jumpers (J11.6 J11B.3 R426.2)
I2S_1_BCLK: 200_Aquila (M1.B20), 800_Jumpers (RA18.1)
I2S_1_BCLK_JMP: 540_Audio (U52.29), 800_Jumpers (J3.1 J3B.1)
I2S_1_D_IN: 200_Aquila (M1.B23), 800_Jumpers (RA18.4)
I2S_1_D_IN_JMP: 540_Audio (U52.31), 800_Jumpers (J3.7 J3B.4)
I2S_1_D_OUT: 200_Aquila (M1.B22), 800_Jumpers (RA18.3)
I2S_1_D_OUT_JMP: 540_Audio (U52.32), 800_Jumpers (J3.5 J3B.3)
I2S_1_MCLK: 200_Aquila (M1.B24), 800_Jumpers (RA19.1)
I2S_1_MCLK_JMP: 540_Audio (U52.28), 800_Jumpers (J3.9 J3B.5)
I2S_1_SYNC: 200_Aquila (M1.B21), 800_Jumpers (RA18.2)
I2S_1_SYNC_JMP: 540_Audio (U52.30), 800_Jumpers (J3.3 J3B.2)
I2S_2_BCLK: 200_Aquila (M1.B26), 810_Jumpers (RA22.4)
I2S_2_BCLK_DSI: 420_MIPI_DSI (J44.42 JP3.1), 810_Jumpers (J12.2 J12B.1)
I2S_2_BCLK_M2B: 400_M2_KeyB (J39.20), 810_Jumpers (J12.10 J12B.5)
I2S_2_D_IN: 200_Aquila (M1.B29), 810_Jumpers (RA22.1)
I2S_2_D_IN_DSI: 420_MIPI_DSI (J44.48), 810_Jumpers (J12.8 J12B.4)
I2S_2_D_IN_M2B: 400_M2_KeyB (J39.24), 810_Jumpers (J12.16 J12B.8)
I2S_2_D_OUT: 200_Aquila (M1.B28), 810_Jumpers (RA22.2)
I2S_2_D_OUT_DSI: 420_MIPI_DSI (J44.46 JP4.1), 810_Jumpers (J12.6 J12B.3)
I2S_2_D_OUT_M2B: 400_M2_KeyB (J39.22), 810_Jumpers (J12.14 J12B.7)
I2S_2_SYNC: 200_Aquila (M1.B27), 810_Jumpers (RA22.3)
I2S_2_SYNC_DSI: 420_MIPI_DSI (J44.44), 810_Jumpers (J12.4 J12B.2)
I2S_2_SYNC_M2B: 400_M2_KeyB (J39.28), 810_Jumpers (J12.12 J12B.6)
JTAG1_TRST#: 200_Aquila (M1.C07), 225_Debug2 (Q31.3), 227_JTAG (R463.1)
JTAG_1_TCK: 200_Aquila (M1.C11), 227_JTAG (J57.2 U59.7)
JTAG_1_TDI: 200_Aquila (M1.C08), 227_JTAG (J57.4 U59.12)
JTAG_1_TDO: 200_Aquila (M1.C10), 227_JTAG (J57.1 U59.4)
JTAG_1_TMS: 200_Aquila (M1.C13), 227_JTAG (J57.3 U59.9)
JTAG_1_VREF: 200_Aquila (M1.C12), 227_JTAG (R287.2)
OSPI_1_IO4: 200_Aquila (M1.B70), 800_Jumpers (RA23.1)
OSPI_1_IO4_JMP: 600_Peripherals (RA5.4), 800_Jumpers (J4.17 J4B.9)
OSPI_1_IO5: 200_Aquila (M1.B71), 800_Jumpers (RA23.2)
OSPI_1_IO5_JMP: 600_Peripherals (RA5.3), 800_Jumpers (J4.19 J4B.10)
OSPI_1_IO6: 200_Aquila (M1.B72), 800_Jumpers (RA23.3)
OSPI_1_IO6_JMP: 600_Peripherals (RA6.4), 800_Jumpers (J4.21 J4B.11)
OSPI_1_IO7: 200_Aquila (M1.B73), 800_Jumpers (RA23.4)
OSPI_1_IO7_JMP: 600_Peripherals (RA6.3), 800_Jumpers (J4.23 J4B.12)
PCIE_1_CLK_N: 200_Aquila (M1.D37), 410_M2_KeyM (J43.53)
PCIE_1_CLK_P: 200_Aquila (M1.D36), 410_M2_KeyM (J43.55)
PCIE_1_CLKREQ: 200_Aquila (M1.C37), 800_Jumpers (RA32.4)
PCIE_1_CLKREQ_JMP: 410_M2_KeyM (D27.1 D27.2 R198.2 R406.1), 800_Jumpers (J14.2 J14B.1)
PCIE_1_L0_RX_N: 200_Aquila (M1.C41), 410_M2_KeyM (J43.41)
PCIE_1_L0_RX_P: 200_Aquila (M1.C40), 410_M2_KeyM (J43.43)
PCIE_1_L0_TX_N: 200_Aquila (M1.D40), 410_M2_KeyM (J43.47)
PCIE_1_L0_TX_P: 200_Aquila (M1.D39), 410_M2_KeyM (J43.49)
PCIE_1_L1_RX_N: 200_Aquila (M1.C44), 410_M2_KeyM (J43.29)
PCIE_1_L1_RX_P: 200_Aquila (M1.C43), 410_M2_KeyM (J43.31)
PCIE_1_L1_TX_N: 200_Aquila (M1.D43), 410_M2_KeyM (J43.35)
PCIE_1_L1_TX_P: 200_Aquila (M1.D42), 410_M2_KeyM (J43.37)
PCIE_1_RESET#: 200_Aquila (M1.C38), 800_Jumpers (RA32.3)
PCIE_1_RESET#_3V: 410_M2_KeyM (R199.1), 215_Translators2 (U44.13)
PCIE_1_RESET#_JMP: 215_Translators2 (RA10.2 U44.4), 800_Jumpers (J14.4 J14B.2)
PCIE_2_CLK_N: 200_Aquila (M1.D28), 400_M2_KeyB (J39.53)
PCIE_2_CLK_P: 200_Aquila (M1.D27), 400_M2_KeyB (J39.55)
PCIE_2_CLKREQ: 200_Aquila (M1.C34), 800_Jumpers (RA32.1)
PCIE_2_CLKREQ_JMP: 400_M2_KeyB (D23.1 D23.2 R182.2 R308.1), 800_Jumpers (J14.8 J14B.4)
PCIE_2_L0_RX_N: 200_Aquila (M1.C29), 400_M2_KeyB (J39.41)
PCIE_2_L0_RX_P: 200_Aquila (M1.C28), 400_M2_KeyB (J39.43)
PCIE_2_L0_TX_N: 200_Aquila (M1.D31), 400_M2_KeyB (J39.47)
PCIE_2_L0_TX_P: 200_Aquila (M1.D30), 400_M2_KeyB (J39.49)
PCIE_2_L1_RX_N: 200_Aquila (M1.C32), 400_M2_KeyB (U41.16)
PCIE_2_L1_RX_P: 200_Aquila (M1.C31), 400_M2_KeyB (U41.17)
PCIE_2_L1_TX_N: 200_Aquila (M1.D34), 400_M2_KeyB (U41.18)
PCIE_2_L1_TX_P: 200_Aquila (M1.D33), 400_M2_KeyB (U41.19)
PCIE_2_RESET#: 200_Aquila (M1.C35), 800_Jumpers (RA35.2)
PCIE_2_RESET#_3V: 400_M2_KeyB (R183.1), 215_Translators2 (U44.12)
PCIE_2_RESET#_JMP: 215_Translators2 (RA10.3 U44.5), 800_Jumpers (J14.10 J14B.5)
PCIE_WAKE#: 200_Aquila (M1.C36), 800_Jumpers (RA32.2)
PCIE_WAKE#_JMP: 400_M2_KeyB (D32.1 D32.2 R301.1 R418.1), 410_M2_KeyM (D47.1 D47.2 R341.1), 800_Jumpers (J14.6 J14B.3)
PWM_1: 200_Aquila (M1.C25), 800_Jumpers (RA16.4)
PWM_2: 200_Aquila (M1.C26), 800_Jumpers (RA16.3)
PWM_3_DSI: 200_Aquila (M1.B46), 800_Jumpers (RA14.4)
PWM_3_DSI_JMP: 420_MIPI_DSI (J44.58), 800_Jumpers (J5.2 J5B.1)
PWM_4_DP: 200_Aquila (M1.B58), 800_Jumpers (RA20.3)
PWR_1V8_MOCI: 200_Aquila (M1.B96), 227_JTAG (R286.2), 810_Jumpers (J9.17 J9A.9)
PWR_EN: 120_Power_2 (6 pins), 140_Power_3 (Q4.1)
QSPI_1_CS1#: 200_Aquila (M1.B66), 800_Jumpers (RA11.3)
QSPI_1_CS1#_JMP: 600_Peripherals (R228.2), 800_Jumpers (J4.5 J4B.3)
QSPI_1_CS2#: 200_Aquila (M1.B62), 800_Jumpers (RA11.2)
QSPI_1_CS2#_JMP: 600_Peripherals (R229.2), 800_Jumpers (J4.3 J4B.2)
QSPI_1_DQS: 200_Aquila (M1.B63), 800_Jumpers (RA11.1)
QSPI_1_DQS_JMP: 600_Peripherals (U56.C3), 800_Jumpers (J4.1 J4B.1)
QSPI_1_IO0: 200_Aquila (M1.B68), 800_Jumpers (RA25.4)
QSPI_1_IO0_JMP: 600_Peripherals (U56.D3), 800_Jumpers (J4.9 J4B.5)
QSPI_1_IO1: 200_Aquila (M1.B67), 800_Jumpers (RA25.3)
QSPI_1_IO1_JMP: 600_Peripherals (U56.D2), 800_Jumpers (J4.11 J4B.6)
QSPI_1_IO2: 200_Aquila (M1.B61), 800_Jumpers (RA25.2)
QSPI_1_IO2_JMP: 600_Peripherals (R238.2 U56.C4), 800_Jumpers (J4.13 J4B.7)
QSPI_1_IO3: 200_Aquila (M1.B60), 800_Jumpers (RA25.1)
QSPI_1_IO3_JMP: 600_Peripherals (U56.D4), 800_Jumpers (J4.15 J4B.8)
QSPI_1_SCK: 200_Aquila (M1.B65), 800_Jumpers (RA11.4)
QSPI_1_SCK_JMP: 600_Peripherals (U56.B2), 800_Jumpers (J4.7 J4B.4)
SD_1_CD#: 200_Aquila (M1.A01), 230_SD_Card (J30.10 U17.4)
SD_1_CLK: 200_Aquila (M1.A05), 230_SD_Card (J30.5 U17.1)
SD_1_CMD: 200_Aquila (M1.A07), 230_SD_Card (J30.2 U18.6)
SD_1_D0: 200_Aquila (M1.A03), 230_SD_Card (J30.7 U17.3)
SD_1_D1: 200_Aquila (M1.A02), 230_SD_Card (J30.8 U17.6)
SD_1_D2: 200_Aquila (M1.A10), 230_SD_Card (J30.9 U18.1)
SD_1_D3: 200_Aquila (M1.A08), 230_SD_Card (J30.1 U18.3)
SD_1_PWR_EN: 200_Aquila (M1.A06), 230_SD_Card (R210.2 R460.1)
SPI_1_CLK: 200_Aquila (M1.D12), 800_Jumpers (RA28.4)
SPI_1_CS: 200_Aquila (M1.D09), 800_Jumpers (RA28.1)
SPI_1_MISO: 200_Aquila (M1.D10), 800_Jumpers (RA28.2)
SPI_1_MOSI: 200_Aquila (M1.D11), 800_Jumpers (RA28.3)
SPI_2_CLK: 200_Aquila (M1.D14), 800_Jumpers (RA31.1)
SPI_2_CS: 200_Aquila (M1.D16), 800_Jumpers (RA31.3)
SPI_2_MISO: 200_Aquila (M1.D15), 800_Jumpers (RA31.2)
SPI_2_MOSI: 200_Aquila (M1.D17), 800_Jumpers (RA31.4)
UART_1_CTS: 200_Aquila (M1.B36), 810_Jumpers (RA38.1)
UART_1_CTS_JMP: 810_Jumpers (J8.8 J8B.4), 700_RS232_RS485 (U77.11)
UART_1_RTS: 200_Aquila (M1.B38), 810_Jumpers (RA38.2)
UART_1_RTS_JMP: 810_Jumpers (J8.6 J8B.3), 700_RS232_RS485 (R384.1 U77.9)
UART_1_RXD: 200_Aquila (M1.B35), 810_Jumpers (RA38.4)
UART_1_RXD_JMP: 810_Jumpers (J8.2 J8B.1), 700_RS232_RS485 (U77.12)
UART_1_TXD: 200_Aquila (M1.B37), 810_Jumpers (RA38.3)
UART_1_TXD_JMP: 810_Jumpers (J8.4 J8B.2), 700_RS232_RS485 (R383.1 U77.10)
UART_2_CTS: 200_Aquila (M1.B32), 810_Jumpers (RA40.1)
UART_2_RTS: 200_Aquila (M1.B34), 810_Jumpers (RA40.2)
UART_2_RTS_JMP: 810_Jumpers (J8.14 J8B.7), 700_RS232_RS485 (R343.1 R407.2 U45.2)
UART_2_RXD: 200_Aquila (M1.B31), 810_Jumpers (RA40.4)
UART_2_RXD_JMP: 810_Jumpers (J8.10 J8B.5), 700_RS232_RS485 (U76.2)
UART_2_TXD: 200_Aquila (M1.B33), 810_Jumpers (RA40.3)
UART_2_TXD_JMP: 810_Jumpers (J8.12 J8B.6), 700_RS232_RS485 (R432.1 U76.5)
UART_3_RXD: 200_Aquila (M1.D19), 810_Jumpers (RA39.1)
UART_3_RXD_JMP: 225_Debug2 (U60.5), 810_Jumpers (J8.18 J8B.9)
UART_3_TXD: 200_Aquila (M1.D20), 810_Jumpers (RA39.2)
UART_3_TXD_JMP: 225_Debug2 (R455.2 U60.6), 810_Jumpers (J8.20 J8B.10)
UART_4_RXD: 200_Aquila (M1.D21), 810_Jumpers (RA39.3)
UART_4_RXD_JMP: 225_Debug2 (U60.3), 810_Jumpers (J8.22 J8B.11)
UART_4_TXD: 200_Aquila (M1.D22), 810_Jumpers (RA39.4)
UART_4_TXD_JMP: 225_Debug2 (R456.2 U60.4), 810_Jumpers (J8.24 J8B.12)
USB3_N: 305_USB_Hub (U27.2), 315_USBC_DFP (L99.3)
USB3_P: 305_USB_Hub (U27.1), 315_USBC_DFP (L99.2)
USB3_PRTPWR: 305_USB_Hub (U27.36), 315_USBC_DFP (R433.2)
USB3_SSRX_N: 305_USB_Hub (U27.7), 315_USBC_DFP (U96.8)
USB3_SSRX_P: 305_USB_Hub (U27.6), 315_USBC_DFP (U96.7)
USB3_SSTX_N: 305_USB_Hub (C131.1), 315_USBC_DFP (U96.4)
USB3_SSTX_P: 305_USB_Hub (C135.1), 315_USBC_DFP (U96.3)
USB4_N: 310_USB3 (L36.3), 305_USB_Hub (U27.9)
USB4_P: 310_USB3 (L36.2), 305_USB_Hub (U27.8)
USB4_PRTPWR: 310_USB3 (R220.2), 305_USB_Hub (U27.35)
USB4_SSRX_N: 310_USB3 (L34.3), 305_USB_Hub (U27.14)
USB4_SSRX_P: 310_USB3 (L34.4), 305_USB_Hub (U27.13)
USB4_SSTX_N: 310_USB3 (L35.3), 305_USB_Hub (C132.1)
USB4_SSTX_P: 310_USB3 (L35.4), 305_USB_Hub (C136.1)
USB5_N: 310_USB3 (L39.3), 305_USB_Hub (U27.18)
USB5_P: 310_USB3 (L39.2), 305_USB_Hub (U27.17)
USB5_PRTPWR: 310_USB3 (R298.2), 305_USB_Hub (U27.34)
USB5_SSRX_N: 310_USB3 (L37.3), 305_USB_Hub (U27.23)
USB5_SSRX_P: 310_USB3 (L37.4), 305_USB_Hub (U27.22)
USB5_SSTX_N: 310_USB3 (L38.3), 305_USB_Hub (C133.1)
USB5_SSTX_P: 310_USB3 (L38.4), 305_USB_Hub (C137.1)
USB6_N: 305_USB_Hub (U27.25), 400_M2_KeyB (J39.9)
USB6_P: 305_USB_Hub (U27.24), 400_M2_KeyB (J39.7)
USB6_SSRX_N: 305_USB_Hub (U27.30), 400_M2_KeyB (U41.12)
USB6_SSRX_P: 305_USB_Hub (U27.29), 400_M2_KeyB (U41.13)
USB6_SSTX_N: 305_USB_Hub (C134.1), 400_M2_KeyB (U41.14)
USB6_SSTX_P: 305_USB_Hub (C138.1), 400_M2_KeyB (U41.15)
USB_1_D_N: 200_Aquila (M1.A71), 300_USB1_OTG (L30.3)
USB_1_D_P: 200_Aquila (M1.A70), 300_USB1_OTG (L30.2)
USB_1_EN: 200_Aquila (M1.B77), 800_Jumpers (RA19.3)
USB_1_INT#: 200_Aquila (M1.B74), 800_Jumpers (RA1.2)
USB_1_INT#_JMP: 300_USB1_OTG (D17.1 D17.2 R118.2), 800_Jumpers (J3.19 J3B.10)
USB_1_OC#: 200_Aquila (M1.B75), 800_Jumpers (RA1.1)
USB_1_OC#_JMP: 300_USB1_OTG (JP1.1), 800_Jumpers (J3.17 J3B.9)
USB_1_SBU_N: 200_Aquila (M1.A67), 300_USB1_OTG (J32.B8 U84.2 U84.9)
USB_1_SBU_P: 200_Aquila (M1.A68), 300_USB1_OTG (J32.A8 U84.1 U84.10)
USB_1_SSRX1_N: 200_Aquila (M1.A61), 300_USB1_OTG (L22.2)
USB_1_SSRX1_P: 200_Aquila (M1.A62), 300_USB1_OTG (L22.1)
USB_1_SSRX2_N: 200_Aquila (M1.A73), 300_USB1_OTG (L28.2)
USB_1_SSRX2_P: 200_Aquila (M1.A74), 300_USB1_OTG (L28.1)
USB_1_SSTX1_N: 200_Aquila (M1.A65), 300_USB1_OTG (L23.1)
USB_1_SSTX1_P: 200_Aquila (M1.A64), 300_USB1_OTG (L23.2)
USB_1_SSTX2_N: 200_Aquila (M1.A77), 300_USB1_OTG (L29.1)
USB_1_SSTX2_P: 200_Aquila (M1.A76), 300_USB1_OTG (L29.2)
USB_1_VBUS: 200_Aquila (M1.B76), 800_Jumpers (RA19.4)
USB_1_VBUS_JMP: 300_USB1_OTG (R114.2 R452.2), 800_Jumpers (J3.15 J3B.8)
USB_2_D_N: 200_Aquila (M1.A85), 305_USB_Hub (U27.46)
USB_2_D_P: 200_Aquila (M1.A86), 305_USB_Hub (U27.45)
USB_2_EN: 200_Aquila (M1.B80), 800_Jumpers (RA19.2)
USB_2_EN_JMP: 305_USB_Hub (R213.2), 800_Jumpers (J3.11 J3B.6)
USB_2_SSRX1_N: 200_Aquila (M1.A82), 305_USB_Hub (C120.1)
USB_2_SSRX1_P: 200_Aquila (M1.A83), 305_USB_Hub (C117.1)
USB_2_SSTX1_N: 200_Aquila (M1.A79), 305_USB_Hub (R462.1)
USB_2_SSTX1_P: 200_Aquila (M1.A80), 305_USB_Hub (R461.1)
VCC_BACKUP: 200_Aquila (M1.B100), 600_Peripherals (R227.2)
